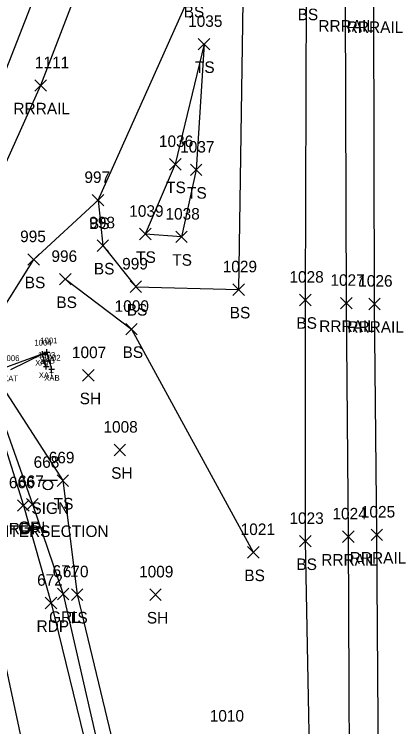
# Model space of a CAD drawing. Extents: x 1764889 to 1767296, y 695936 to 698960.
# Drawn here: x 1766350.6 to 1766418.5, y 696517.3 to 696640.9 of the extents above; entities that cross this region are included whole.
import ezdxf

# ---------------------------------------------------------------- set-up
doc = ezdxf.new("R2010")
doc.units = 0
for name, color, linetype in [('B_A', 7, 'Continuous'), ('B_I', 7, 'Continuous'), ('B_TIC', 7, 'Continuous'), ('BSUBM', 7, 'Continuous'), ('L_A', 7, 'Continuous'), ('L_I', 7, 'Continuous'), ('L_TIC', 7, 'Continuous'), ('LELB', 7, 'Continuous'), ('P_A', 7, 'Continuous'), ('P_I', 7, 'Continuous'), ('P_TIC', 7, 'Continuous'), ('PET', 7, 'Continuous'), ('PRC', 7, 'Continuous'), ('R_A', 7, 'Continuous'), ('R_I', 7, 'Continuous'), ('R_TIC', 7, 'Continuous'), ('RGR', 7, 'Continuous'), ('RR', 7, 'Continuous'), ('S_A', 7, 'Continuous'), ('S_C', 7, 'Continuous'), ('S_I', 7, 'Continuous'), ('SSGN', 7, 'Continuous')]:
    doc.layers.add(name, color=color, linetype=linetype)

msp = doc.modelspace()

# ---------------------------------------------------------------- linework, layer by layer
at = {"layer": 'B_TIC'}
for p, q in [((1766356.24, 696582.34), (1766356.31, 696582.34)), ((1766355.5, 696581.96), (1766355.58, 696581.96)), ((1766356.13, 696579.83), (1766356.2, 696579.83)), ((1766357.06, 696579.35), (1766357.13, 696579.35))]:
    msp.add_line(p, q, dxfattribs=at)
for points in [[(1766355.5, 696581.46), (1766355.5, 696582.46)], [(1766355.73, 696582.34), (1766356.73, 696582.34)], [(1766356.23, 696581.84), (1766356.23, 696582.84)], [(1766355, 696581.96), (1766356, 696581.96)], [(1766355.62, 696579.83), (1766356.62, 696579.83)], [(1766356.12, 696579.33), (1766356.12, 696580.33)], [(1766357.05, 696578.85), (1766357.05, 696579.85)], [(1766356.55, 696579.35), (1766357.55, 696579.35)]]:
    msp.add_lwpolyline(points, dxfattribs=at)
at = {"layer": 'BSUBM'}
for points in [[(1766315.59, 696518.3), (1766327.77, 696535.58), (1766326.19, 696547.42), (1766344.21, 696577.89), (1766356.23, 696582.34), (1766357.05, 696579.35)], [(1766356.12, 696579.83), (1766355.5, 696581.96), (1766349.94, 696579.26)]]:
    msp.add_lwpolyline(points, dxfattribs=at)
at = {"layer": 'L_TIC'}
for points in [[(1766382.5, 696634.75), (1766384.5, 696636.75)], [(1766384.5, 696634.75), (1766382.5, 696636.75)], [(1766382.5, 696634.75), (1766384.5, 696636.75)], [(1766384.5, 696634.75), (1766382.5, 696636.75)], [(1766377.5, 696613.9), (1766379.5, 696615.9)], [(1766379.5, 696613.9), (1766377.5, 696615.9)], [(1766381.13, 696612.94), (1766383.13, 696614.94)], [(1766383.13, 696612.94), (1766381.13, 696614.94)], [(1766364.1, 696607.67), (1766366.1, 696609.67)], [(1766366.1, 696607.67), (1766364.1, 696609.67)], [(1766364.1, 696607.67), (1766366.1, 696609.67)], [(1766366.1, 696607.67), (1766364.1, 696609.67)], [(1766372.3, 696601.8), (1766374.3, 696603.8)], [(1766374.3, 696601.8), (1766372.3, 696603.8)], [(1766372.3, 696601.8), (1766374.3, 696603.8)], [(1766374.3, 696601.8), (1766372.3, 696603.8)], [(1766378.57, 696601.31), (1766380.57, 696603.31)], [(1766380.57, 696601.31), (1766378.57, 696603.31)], [(1766364.94, 696599.8), (1766366.94, 696601.8)], [(1766366.94, 696599.8), (1766364.94, 696601.8)], [(1766352.95, 696597.4), (1766354.95, 696599.4)], [(1766354.95, 696597.4), (1766352.95, 696599.4)], [(1766358.44, 696593.97), (1766360.44, 696595.97)], [(1766360.44, 696593.97), (1766358.44, 696595.97)], [(1766370.66, 696592.66), (1766372.66, 696594.66)], [(1766372.66, 696592.66), (1766370.66, 696594.66)], [(1766388.51, 696592.17), (1766390.51, 696594.17)], [(1766390.51, 696592.17), (1766388.51, 696594.17)], [(1766400.07, 696590.37), (1766402.07, 696592.37)], [(1766402.07, 696590.37), (1766400.07, 696592.37)], [(1766369.92, 696585.31), (1766371.92, 696587.31)], [(1766371.92, 696585.31), (1766369.92, 696587.31)], [(1766362.43, 696577.28), (1766364.43, 696579.28)], [(1766364.43, 696577.28), (1766362.43, 696579.28)], [(1766367.89, 696564.35), (1766369.89, 696566.35)], [(1766369.89, 696564.35), (1766367.89, 696566.35)], [(1766358.01, 696559.03), (1766360.01, 696561.03)], [(1766360.01, 696559.03), (1766358.01, 696561.03)], [(1766400.07, 696548.52), (1766402.07, 696550.52)], [(1766402.07, 696548.52), (1766400.07, 696550.52)], [(1766391.04, 696546.59), (1766393.04, 696548.59)], [(1766393.04, 696546.59), (1766391.04, 696548.59)], [(1766360.49, 696539.26), (1766362.49, 696541.26)], [(1766362.49, 696539.26), (1766360.49, 696541.26)], [(1766374.08, 696539.24), (1766376.08, 696541.24)], [(1766376.08, 696539.24), (1766374.08, 696541.24)]]:
    msp.add_lwpolyline(points, dxfattribs=at)
at = {"layer": 'LELB'}
for points in [[(1766311.88, 696556.72), (1766333.81, 696592.11), (1766361.34, 696662.5)], [(1766365.1, 696608.67), (1766365.94, 696600.8), (1766371.66, 696593.66), (1766389.51, 696593.17), (1766390.32, 696647.01), (1766381.52, 696645.38)], [(1766341.44, 696578.46), (1766353.95, 696598.4), (1766365.1, 696608.67), (1766381.52, 696645.38)], [(1766376.43, 696369.05), (1766399.38, 696421.91), (1766400.57, 696461.93), (1766402.32, 696486.13), (1766401.07, 696549.52), (1766401.07, 696591.37), (1766401.28, 696644.9)], [(1766383.5, 696635.75), (1766378.5, 696614.9), (1766373.3, 696602.8)], [(1766383.5, 696635.75), (1766382.13, 696613.94), (1766379.57, 696602.31), (1766373.3, 696602.8)], [(1766359.44, 696594.97), (1766370.92, 696586.31), (1766392.04, 696547.59)], [(1766348.57, 696576.19), (1766359.01, 696560.03), (1766361.49, 696540.26), (1766368.46, 696511.17), (1766371.63, 696487)]]:
    msp.add_lwpolyline(points, dxfattribs=at)
at = {"layer": 'P_TIC'}
for points in [[(1766351.15, 696554.7), (1766353.15, 696556.7)], [(1766353.15, 696554.7), (1766351.15, 696556.7)], [(1766355.95, 696537.79), (1766357.95, 696539.79)], [(1766357.95, 696537.79), (1766355.95, 696539.79)]]:
    msp.add_lwpolyline(points, dxfattribs=at)
at = {"layer": 'PET'}
msp.add_lwpolyline([(1766331.65, 696550.27), (1766338.9, 696564.49), (1766345.39, 696577.08), (1766352.15, 696555.7), (1766356.95, 696538.79), (1766363.97, 696510.15), (1766367.19, 696487.5)], dxfattribs=at)
at = {"layer": 'PRC'}
msp.add_lwpolyline([(1766338.9, 696564.49), (1766342.21, 696553.11), (1766347.54, 696534.73), (1766353.36, 696507.93), (1766356.46, 696477.18), (1766356.12, 696449.17), (1766352.9, 696426.11), (1766347.27, 696403.75), (1766338.09, 696378.93), (1766326.54, 696354.51), (1766322.36, 696346.4)], dxfattribs=at)
at = {"layer": 'R_TIC'}
for points in [[(1766354.14, 696627.57), (1766356.14, 696629.57)], [(1766356.14, 696627.57), (1766354.14, 696629.57)], [(1766407.18, 696589.82), (1766409.18, 696591.82)], [(1766409.18, 696589.82), (1766407.18, 696591.82)], [(1766412.06, 696589.68), (1766414.06, 696591.68)], [(1766414.06, 696589.68), (1766412.06, 696591.68)], [(1766352.71, 696554.93), (1766354.71, 696556.93)], [(1766354.71, 696554.93), (1766352.71, 696556.93)], [(1766412.47, 696549.63), (1766414.47, 696551.63)], [(1766414.47, 696549.63), (1766412.47, 696551.63)], [(1766407.53, 696549.3), (1766409.53, 696551.3)], [(1766409.53, 696549.3), (1766407.53, 696551.3)], [(1766358.06, 696539.35), (1766360.06, 696541.35)], [(1766360.06, 696539.35), (1766358.06, 696541.35)]]:
    msp.add_lwpolyline(points, dxfattribs=at)
at = {"layer": 'RGR'}
msp.add_lwpolyline([(1766346.64, 696575.95), (1766353.71, 696555.93), (1766359.06, 696540.35), (1766365.92, 696510.33), (1766368.76, 696487.08)], dxfattribs=at)
at = {"layer": 'RR'}
for points in [[(1766414.51, 696927.61), (1766410.63, 696876.83), (1766407.5, 696845.7), (1766404.42, 696820.76), (1766396.99, 696776.65), (1766388.17, 696735.44), (1766377.78, 696694.21), (1766366.7, 696658.73), (1766355.14, 696628.57), (1766340.23, 696595.43), (1766321.37, 696561.38), (1766312.46, 696547.47), (1766299.86, 696528.94)], [(1766410.41, 696332.08), (1766409.46, 696420.45), (1766408.85, 696485.76), (1766408.53, 696550.3), (1766408.18, 696590.82), (1766408.03, 696642.92), (1766408.33, 696712.56), (1766409.02, 696750.78), (1766409.91, 696798.98)], [(1766415.4, 696332.21), (1766414.47, 696421.49), (1766413.91, 696486.12), (1766413.47, 696550.63), (1766413.06, 696590.68), (1766412.95, 696642.7), (1766413.23, 696713.18), (1766413.82, 696750.29), (1766414.9, 696799.38)]]:
    msp.add_lwpolyline(points, dxfattribs=at)
at = {"layer": 'SSGN'}
for p, q in [((1766354.76, 696560.1), (1766358.1, 696560.1)), ((1766356.41, 696559.27), (1766356.41, 696559.27))]:
    msp.add_line(p, q, dxfattribs=at)
msp.add_circle((1766356.41, 696559.27), 0.833, dxfattribs=at)

# ---------------------------------------------------------------- texts
at = {"layer": 'B_A'}
for s, p in [('XAB', (1766354.95, 696580.34)), ('XAT', (1766354.2, 696579.96)), ('XAT', (1766354.83, 696577.83)), ('XAT', (1766348.64, 696577.26)), ('XAT', (1766348.64, 696577.26)), ('XAB', (1766355.77, 696577.35))]:
    msp.add_text(s, height=1, dxfattribs=at).set_placement(p)
at = {"layer": 'B_I'}
for s, p in [('1001', (1766355.09, 696583.84)), ('1004', (1766354.07, 696583.46)), ('1003', (1766354.7, 696581.33)), ('1006', (1766348.49, 696580.76)), ('1006', (1766348.49, 696580.76)), ('1002', (1766355.63, 696580.85))]:
    msp.add_text(s, height=1, dxfattribs=at).set_placement(p)
at = {"layer": 'L_A'}
for s, p in [('BS', (1766379.96, 696640.38)), ('BS', (1766379.96, 696640.38)), ('BS', (1766399.72, 696639.9)), ('TS', (1766381.91, 696630.75)), ('TS', (1766381.91, 696630.75)), ('TS', (1766376.91, 696609.9)), ('TS', (1766380.54, 696608.94)), ('BS', (1766363.54, 696603.67)), ('BS', (1766363.54, 696603.67)), ('TS', (1766371.71, 696597.8)), ('TS', (1766371.71, 696597.8)), ('TS', (1766377.98, 696597.31)), ('BS', (1766364.38, 696595.8)), ('BS', (1766352.39, 696593.4)), ('BS', (1766357.88, 696589.97)), ('BS', (1766370.1, 696588.66)), ('BS', (1766387.95, 696588.17)), ('BS', (1766399.51, 696586.37)), ('BS', (1766369.36, 696581.31)), ('SH', (1766361.92, 696573.28)), ('SH', (1766367.38, 696560.35)), ('TS', (1766357.42, 696555.03)), ('BS', (1766399.51, 696544.52)), ('BS', (1766390.48, 696542.59)), ('TS', (1766359.9, 696535.26)), ('SH', (1766373.57, 696535.24))]:
    msp.add_text(s, height=2, dxfattribs=at).set_placement(p)
at = {"layer": 'L_I'}
for s, p in [('1035', (1766380.73, 696638.75)), ('1035', (1766380.73, 696638.75)), ('1036', (1766375.67, 696617.9)), ('1037', (1766379.35, 696616.94)), ('997', (1766362.74, 696611.67)), ('997', (1766362.74, 696611.67)), ('1039', (1766370.52, 696605.8)), ('1039', (1766370.52, 696605.8)), ('1038', (1766376.8, 696605.31)), ('998', (1766363.58, 696603.8)), ('995', (1766351.59, 696601.4)), ('996', (1766357.02, 696597.97)), ('999', (1766369.29, 696596.66)), ('1029', (1766386.73, 696596.17)), ('1028', (1766398.3, 696594.37)), ('1000', (1766367.98, 696589.31)), ('1007', (1766360.58, 696581.28)), ('1008', (1766366.04, 696568.35)), ('669', (1766356.55, 696563.03)), ('1023', (1766398.3, 696552.52)), ('1021', (1766389.84, 696550.59)), ('670', (1766358.99, 696543.26)), ('1009', (1766372.22, 696543.24)), ('1010', (1766384.48, 696518.23))]:
    msp.add_text(s, height=2, dxfattribs=at).set_placement(p)
at = {"layer": 'P_A'}
for p in [(1766349.64, 696550.7), (1766354.44, 696533.79)]:
    msp.add_text('RDP', height=2, dxfattribs=at).set_placement(p)
at = {"layer": 'P_I'}
for s, p in [('666', (1766349.64, 696558.7)), ('672', (1766354.54, 696541.79))]:
    msp.add_text(s, height=2, dxfattribs=at).set_placement(p)
at = {"layer": 'R_A'}
for s, p in [('RRRAIL', (1766403.32, 696637.92)), ('RRRAIL', (1766408.24, 696637.7)), ('RRRAIL', (1766350.43, 696623.57)), ('RRRAIL', (1766403.47, 696585.82)), ('RRRAIL', (1766408.35, 696585.68)), ('GRL', (1766351.25, 696550.93)), ('RRRAIL', (1766408.76, 696545.63)), ('RRRAIL', (1766403.82, 696545.3)), ('GRL', (1766356.61, 696535.35))]:
    msp.add_text(s, height=2, dxfattribs=at).set_placement(p)
at = {"layer": 'R_I'}
for s, p in [('1111', (1766354.15, 696631.57)), ('1027', (1766405.41, 696593.82)), ('1026', (1766410.24, 696593.68)), ('667', (1766351.25, 696558.93)), ('1024', (1766405.76, 696553.3)), ('1025', (1766410.69, 696553.63)), ('671', (1766357.22, 696543.35))]:
    msp.add_text(s, height=2, dxfattribs=at).set_placement(p)
at = {"layer": 'S_A'}
msp.add_text('SIGN', height=2, dxfattribs=at).set_placement((1766353.55, 696554.25))
at = {"layer": 'S_C'}
msp.add_text('T INTERSECTION', height=2, dxfattribs=at).set_placement((1766344.65, 696550.25))
at = {"layer": 'S_I'}
msp.add_text('668', height=2, dxfattribs=at).set_placement((1766353.93, 696562.25))

doc.saveas('drawing.dxf')
